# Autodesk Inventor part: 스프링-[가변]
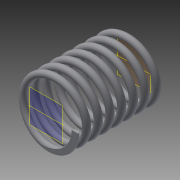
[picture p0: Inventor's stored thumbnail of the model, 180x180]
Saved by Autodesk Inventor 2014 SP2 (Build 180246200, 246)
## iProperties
Created: 2015-01
Part Number: 스프링-[가변]
Material: 강철, 탄소
Document SubType Name: Modeling
Designer: 201-09
Density: 7.87 g/cm^3
Appearance: 반연마
Author: 201-09
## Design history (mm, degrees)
node "작업 평면1"
node "작업축1"
  node "작업 평면2"
node "작업축2"
sketch "스케치1"
  geometry: L1 (-3.9, 8.693)-(23.4, 8.693) reference; L2 (0, -51.288)-(0, 8.548) reference; C1 r 2 at (17.5, -39.807); 3 further points; 1 other entity
  constraints: 1 centre point, 2 other
  dimensions: "d2" = 4 diameter of C1; "d3" = 17.5 distance from line of C1.centre L2; "d4" = 48.5 dimension on L1 (derived)
feature "코일1" sketch "스케치1" pitch "d5" = 10; turns "d7" = 7.5; dims "d6" = 48.5 (= d4), "d8" = 0, angle "d9" = 90 deg, angle "d10" = 90 deg, "d11" = 0, "d12" = 0
feature "분할1"
feature "분할2"
node "솔리드1"
other parameters: "d0" = 0, "d1" = 53.5
